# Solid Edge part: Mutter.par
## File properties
Dokumentum tartalom típus: 0
Last saved by: psaghy
Revision: 77
Sűrűség: 0,000 kg/m^3
Pontosság: 0,990
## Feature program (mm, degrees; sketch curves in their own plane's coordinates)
base feature "unnamed BaseFeature 1"
sketch for "Furat_1" plane through (6, 0, 0) normal (1, 0, 0) x-axis (0, -1, 0)
hole "Furat_1" through  StartChamferOffset = 0.39 mm; StartChamferAngle = 45 deg
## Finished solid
Body 1: solid body, 23 faces, 47 edges, 26 vertices.
  Faces by surface: cone 14, plane 8, cylinder 1
  Edges by curve: spline 24, circle 16, line 7
Bounding box of the edges (mm): 6.000 x 19.630 x 17.000, from (0, -9.815, -8.5) to (6, 9.815, 8.5).
Cylindrical faces by radius (mm): R4.3235 x1
Conical faces (half-angle, radius in mm at the cone's reference point): 45 deg R4.7135 x1, 60 deg R4.6618 x1, 60 deg R9.1575 x12
Planar faces by outward normal: +x 1, +z 1, -x 1, -z 1, oblique 4
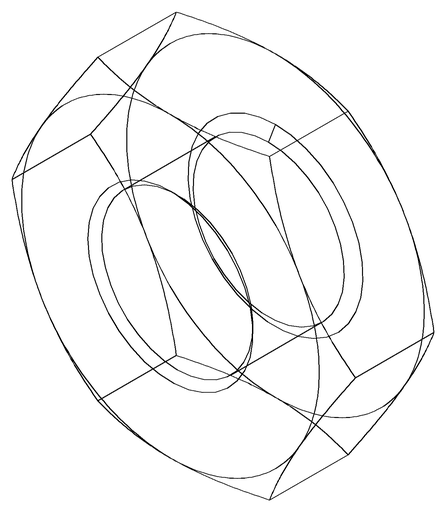
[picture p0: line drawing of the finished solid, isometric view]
